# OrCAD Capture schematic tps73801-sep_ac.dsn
size A
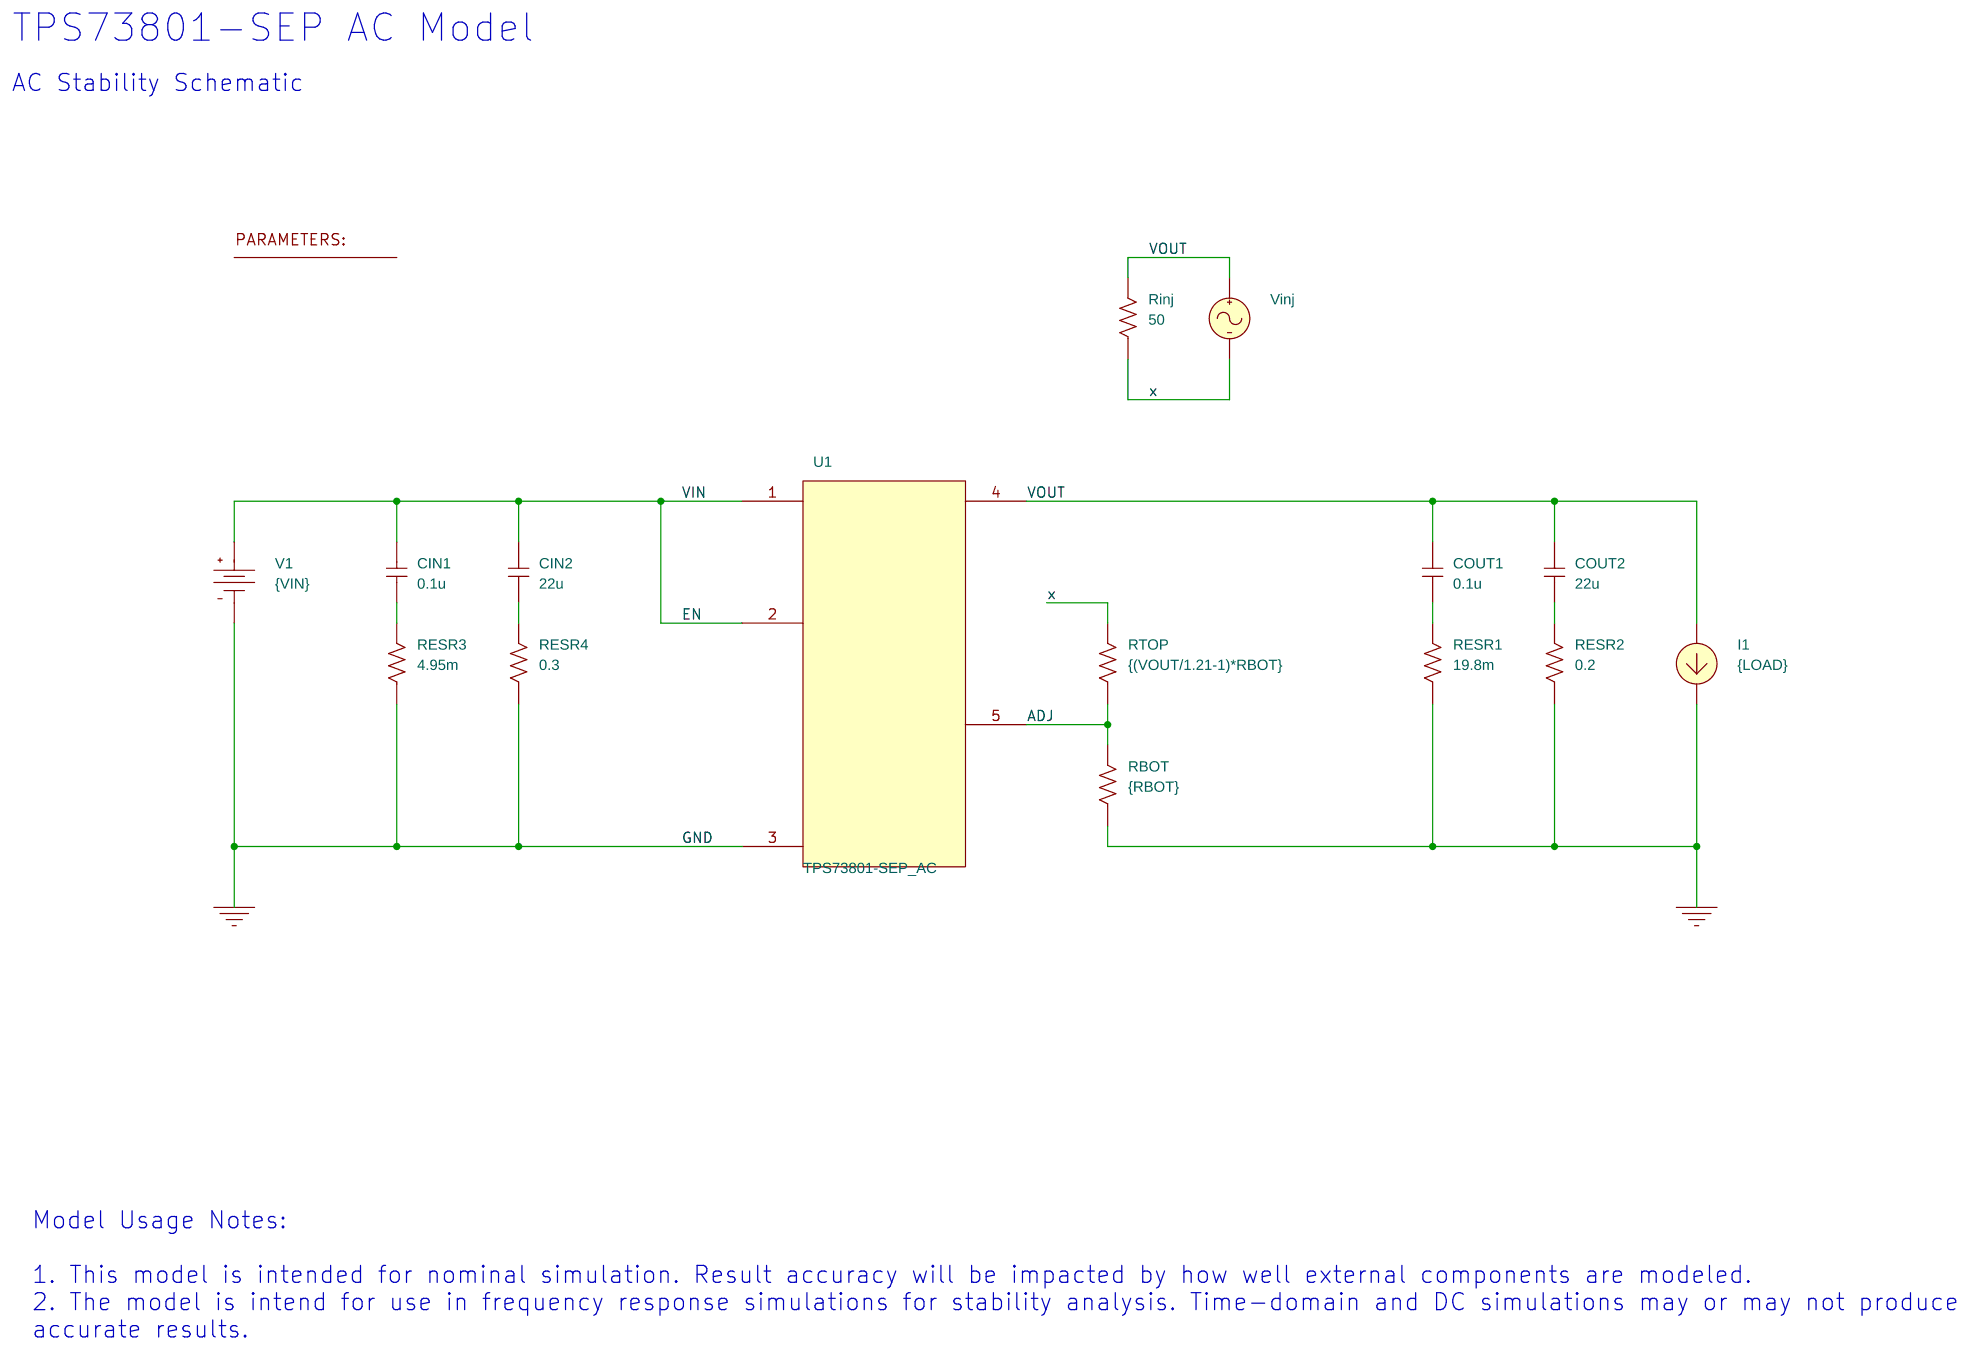
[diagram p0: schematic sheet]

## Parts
1  PARAM
CIN1  0.1u  [cap196]
CIN2  22u  [cap196]
COUT1  0.1u  [cap196]
COUT2  22u  [cap196]
I1  IDC
RBOT  {RBOT}  [AXRC05]
RESR1  19.8m  [AXRC05]
RESR2  0.2  [AXRC05]
RESR3  4.95m  [AXRC05]
RESR4  0.3  [AXRC05]
Rinj  50  [AXRC05]
RTOP  {(VOUT/1.21-1)*RBOT}  [AXRC05]
U1  TPS73801-SEP_AC
V1  VDC
Vinj  VAC

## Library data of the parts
1 = PARAM: RBOT: 10k; VIN: 3.3; VOUT: 2.5
CIN1 CIN2 COUT1 COUT2 = C
I1 = IDC: DC: {LOAD}
RBOT RESR1-RESR4 Rinj RTOP = R
U1 = TPS73801-SEP_AC_7
V1 = VDC: DC: {VIN}
Vinj = VAC

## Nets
0: I1.2(-) RBOT.1 RESR1.1 RESR2.1 RESR3.1 RESR4.1 U1.3(GND) V1.1(-)
ADJ: RBOT.2 RTOP.1 U1.5(ADJ)
EN: CIN1.1 CIN2.1 U1.1(IN) U1.2(EN) V1.0(+)
VOUT: COUT1.1 COUT2.1 I1.1(+) Rinj.2 U1.4(OUT) Vinj.1(+)
x: Rinj.1 RTOP.2 Vinj.2(-)
N00982: COUT1.2 RESR1.2
N01227: COUT2.2 RESR2.2
N01483: CIN1.2 RESR3.2
N01487: CIN2.2 RESR4.2

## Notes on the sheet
- TPS73801-SEP AC Model
- AC Stability Schematic
- Model Usage Notes:
  1. This model is intended for nominal simulation. Result accuracy will be impacted by how well external components are modeled.
  2. The model is intend for use in frequency response simulations for stability analysis. Time-domain and DC simulations may or may not produce
  accurate results.
